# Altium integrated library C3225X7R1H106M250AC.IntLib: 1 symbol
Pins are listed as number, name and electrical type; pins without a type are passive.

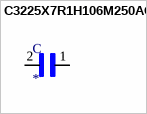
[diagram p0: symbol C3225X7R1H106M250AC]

## C3225X7R1H106M250AC
designator C
10ÂµF Â±20% 50V Ceramic Capacitor X7R 1210 _3225 Metric_; MP: C3225X7R1H106M250AC; MF: TDK
footprint CAPC3225X280N
pins: 1, 2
